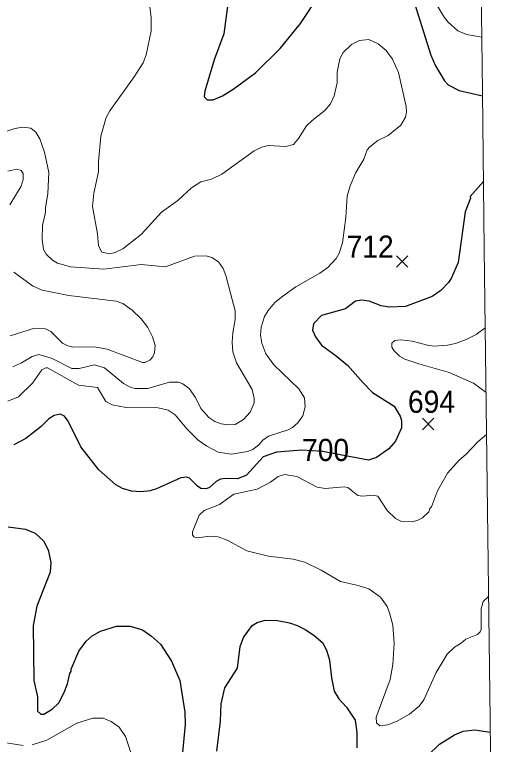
# Model space of a CAD drawing. Extents: x 265 to 291.4, y 7731.5 to 7759.6.
# Drawn here: x 289.561 to 291.321, y 7743.657 to 7746.284 of the extents above; entities that cross this region are included whole.
import ezdxf
from ezdxf.enums import TextEntityAlignment as Align

# ---------------------------------------------------------------- set-up
doc = ezdxf.new("R2010")
doc.units = 0
doc.header["$LTSCALE"] = 0.032
for name, color, linetype, lineweight in [('1', 7, 'Continuous', 25), ('2', 7, 'Continuous', 13), ('21', 7, 'Continuous', 25), ('61', 7, 'Continuous', 13), ('63', 7, 'Continuous', 25)]:
    doc.layers.add(name, color=color, linetype=linetype, lineweight=lineweight)

msp = doc.modelspace()

# ---------------------------------------------------------------- linework, layer by layer
at = {"layer": '1'}
for points in [[(290.2756, 7745.9765), (290.3098, 7745.9916), (290.348, 7746.0155), (290.4276, 7746.0744), (290.5166, 7746.1611), (290.5906, 7746.2518), (290.725, 7746.4554)], [(290.9876, 7746.3679), (291.0599, 7746.1372), (291.0759, 7746.0991), (291.1085, 7746.045), (291.122, 7746.0314), (291.1618, 7746.0099), (291.2452, 7745.9917)], [(290.3281, 7746.3218), (290.3146, 7746.2144), (290.2788, 7746.1213), (290.2462, 7746.0084), (290.243, 7745.9877), (290.2541, 7745.9773), (290.2756, 7745.9765)], [(291.249, 7745.683), (291.2015, 7745.6289), (291.2023, 7745.6225), (291.1825, 7745.574), (291.1578, 7745.3911), (291.1331, 7745.3338), (291.1236, 7745.3195), (291.095, 7745.2908), (291.0639, 7745.2693), (290.9685, 7745.2335), (290.9096, 7745.2304), (290.881, 7745.2351), (290.838, 7745.2526), (290.8094, 7745.2558), (290.7879, 7745.2526), (290.7521, 7745.2248), (290.6654, 7745.2009), (290.6376, 7745.1707), (290.6336, 7745.1484), (290.6439, 7745.1238), (290.6654, 7745.0943), (290.7187, 7745.0561), (290.7609, 7745.0211), (290.8141, 7744.9591), (290.8499, 7744.9233), (290.9279, 7744.8748), (290.9494, 7744.839), (290.9534, 7744.8231), (290.9541, 7744.7968), (290.9319, 7744.7483), (290.908, 7744.7213), (290.8635, 7744.6902), (290.8348, 7744.6807), (290.6693, 7744.7117), (290.5956, 7744.7157), (290.5039, 7744.7085), (290.4554, 7744.6918), (290.3957, 7744.6258), (290.3639, 7744.6131), (290.3194, 7744.6147), (290.3018, 7744.6115), (290.2868, 7744.6035), (290.2621, 7744.582), (290.251, 7744.5773), (290.2319, 7744.5781), (290.2199, 7744.586), (290.1905, 7744.6155), (290.181, 7744.6186), (290.1595, 7744.617), (290.0712, 7744.5765), (290.0489, 7744.5701), (290.0155, 7744.5661), (289.9821, 7744.5685), (289.9495, 7744.5781), (289.9256, 7744.5916), (289.8643, 7744.6449), (289.7999, 7744.7276), (289.7538, 7744.8207), (289.7403, 7744.8382), (289.7251, 7744.8453), (289.7037, 7744.8414), (289.6838, 7744.8286), (289.6567, 7744.8016), (289.6018, 7744.7579), (289.5581, 7744.7356)], [(289.5382, 7744.4405), (289.6003, 7744.4317), (289.6353, 7744.4174)], [(289.6353, 7744.4174), (289.6655, 7744.3903), (289.6822, 7744.3569), (289.6909, 7744.3124), (289.6885, 7744.2774), (289.6408, 7744.1549), (289.6273, 7744.0849)], [(290.2891, 7743.6331), (290.3018, 7743.7412), (290.305, 7743.8033), (290.3178, 7743.8606), (290.3639, 7743.9322), (290.3727, 7744.0101), (290.3854, 7744.0419), (290.4164, 7744.0849), (290.4339, 7744.096), (290.4626, 7744.1048), (290.5071, 7744.1032), (290.5501, 7744.0952), (290.5787, 7744.0857), (290.6073, 7744.0713), (290.6384, 7744.0507), (290.6702, 7744.0228), (290.6853, 7743.9926), (290.6948, 7743.9608), (290.702, 7743.8972), (290.7115, 7743.8494), (290.7282, 7743.8208), (290.7561, 7743.7914), (290.7871, 7743.7444), (290.7935, 7743.6999), (290.7927, 7743.645)], [(289.6273, 7744.0849), (289.6305, 7743.8876), (289.6432, 7743.8287), (289.6432, 7743.777), (289.6559, 7743.7667), (289.6663, 7743.7659), (289.6965, 7743.7842), (289.7196, 7743.8072), (289.7386, 7743.8415), (289.7514, 7743.8749), (289.7593, 7743.913), (289.7641, 7743.9194), (289.7641, 7743.9282), (289.7919, 7743.9926), (289.8182, 7744.0284), (289.8405, 7744.0483), (289.8707, 7744.0642), (289.928, 7744.0825), (289.9773, 7744.0825), (290.0219, 7744.069), (290.0537, 7744.0467), (290.0863, 7744.0181), (290.1253, 7743.9568), (290.1555, 7743.8876), (290.1738, 7743.7731), (290.1746, 7743.7285), (290.165, 7743.6283)], [(291.048, 7743.6156), (291.0902, 7743.6577), (291.1443, 7743.6919), (291.1753, 7743.7054), (291.2183, 7743.7094), (291.273, 7743.7019)]]:
    msp.add_lwpolyline(points, dxfattribs=at)
at = {"layer": '2'}
for points in [[(291.2427, 7746.2019), (291.188, 7746.212), (291.1562, 7746.2255), (291.122, 7746.2558), (291.1069, 7746.2741), (291.0409, 7746.3854), (290.9868, 7746.492), (290.9725, 7746.5302), (290.9645, 7746.5652), (290.9597, 7746.6368), (290.9709, 7746.6925), (290.982, 7746.7243), (291.0011, 7746.7521), (291.0297, 7746.7792), (291.0767, 7746.8086), (291.1467, 7746.8396), (291.2199, 7746.8818), (291.2343, 7746.8892)], [(290.0401, 7746.3743), (290.0521, 7746.2725), (290.0521, 7746.2247), (290.0346, 7746.1388), (290.0234, 7746.1102), (289.9916, 7746.0593), (289.9033, 7745.9368), (289.8906, 7745.9129), (289.8715, 7745.8461), (289.8628, 7745.7554), (289.8628, 7745.7172), (289.846, 7745.6409), (289.8413, 7745.5931), (289.8596, 7745.4945), (289.8635, 7745.4515), (289.8755, 7745.4285), (289.9025, 7745.4229), (289.9232, 7745.4269), (289.9503, 7745.4404), (290.0179, 7745.4937), (290.0895, 7745.5732), (290.1483, 7745.6146), (290.1977, 7745.6607), (290.2319, 7745.6822), (290.2701, 7745.691), (290.3066, 7745.7093), (290.4236, 7745.7936), (290.4514, 7745.8071), (290.4737, 7745.8127), (290.5373, 7745.8095), (290.5652, 7745.8166), (290.5827, 7745.8373), (290.6121, 7745.8827), (290.632, 7745.9026), (290.6773, 7745.9384), (290.6988, 7745.9622), (290.7115, 7745.9909), (290.7227, 7746.0386), (290.7227, 7746.0768), (290.7322, 7746.1245), (290.7434, 7746.1468), (290.7736, 7746.1762), (290.803, 7746.1905), (290.8364, 7746.1945), (290.8699, 7746.1778), (290.8985, 7746.1539), (290.9215, 7746.1229), (290.943, 7746.0752), (290.9709, 7745.9527), (290.9717, 7745.9336), (290.9677, 7745.9145), (290.951, 7745.8859), (290.9064, 7745.8485), (290.8683, 7745.8302), (290.8396, 7745.8079), (290.8301, 7745.7968), (290.8181, 7745.7634), (290.7895, 7745.7156), (290.7688, 7745.6679), (290.7577, 7745.6297), (290.7529, 7745.5534), (290.741, 7745.4627), (290.729, 7745.4245), (290.7187, 7745.4054), (290.6885, 7745.3736), (290.6598, 7745.3537), (290.5739, 7745.3036), (290.5262, 7745.2709), (290.4984, 7745.2479), (290.4737, 7745.2193), (290.4602, 7745.197), (290.4482, 7745.1588), (290.4466, 7745.1302), (290.4506, 7745.1015), (290.4649, 7745.0633)], [(289.6838, 7745.7156), (289.6687, 7745.7888), (289.6512, 7745.8365), (289.6368, 7745.8604), (289.6193, 7745.8755), (289.5907, 7745.8787), (289.5621, 7745.8739)], [(289.5621, 7745.8739), (289.5112, 7745.8572)], [(289.5438, 7745.5995), (289.5851, 7745.6663), (289.5923, 7745.6902), (289.5923, 7745.7117), (289.5843, 7745.722), (289.5684, 7745.7268), (289.5366, 7745.7204)], [(289.5541, 7745.0164), (289.5859, 7745.0299), (289.6241, 7745.0538), (289.648, 7745.0601), (289.6957, 7745.0458), (289.7673, 7745.01), (289.7928, 7745.01), (289.8484, 7745.0236), (289.885, 7745.0124), (289.9535, 7744.9559), (289.9773, 7744.9424), (289.9932, 7744.9376), (290.0409, 7744.9376), (290.1189, 7744.9607), (290.1507, 7744.9607), (290.1666, 7744.9551), (290.1897, 7744.9384), (290.212, 7744.9058), (290.2319, 7744.8661), (290.2597, 7744.8342), (290.2812, 7744.8191), (290.3051, 7744.8104), (290.3289, 7744.8072), (290.3544, 7744.8088), (290.3854, 7744.8271), (290.4093, 7744.8533), (290.4228, 7744.8867), (290.4236, 7744.9026), (290.4156, 7744.9345), (290.3599, 7745.0299), (290.3464, 7745.0697), (290.344, 7745.1047), (290.3464, 7745.1381), (290.3552, 7745.1858), (290.3552, 7745.2177), (290.3217, 7745.3449), (290.3122, 7745.3704), (290.2955, 7745.3934), (290.2708, 7745.4094), (290.2502, 7745.4157), (290.208, 7745.4141), (290.1046, 7745.3759), (290.0171, 7745.3847), (289.8819, 7745.3672), (289.7625, 7745.3759), (289.7148, 7745.3895), (289.6973, 7745.3998), (289.675, 7745.4213), (289.6655, 7745.4388), (289.6599, 7745.4746), (289.6615, 7745.5247), (289.6718, 7745.5724), (289.6718, 7745.5884), (289.6806, 7745.6393), (289.6838, 7745.7156)], [(289.5446, 7745.1278), (289.6321, 7745.1548), (289.6719, 7745.1532), (289.6909, 7745.1429), (289.7339, 7745.1015), (289.753, 7745.0912), (289.7705, 7745.0864), (289.8469, 7745.088), (289.8946, 7745.08), (290.0219, 7745.0315), (290.0298, 7745.0315), (290.0473, 7745.0403), (290.0584, 7745.0522), (290.0648, 7745.0665), (290.0672, 7745.0928), (290.0568, 7745.1238), (290.0401, 7745.1572), (290.0163, 7745.189), (289.9845, 7745.22), (289.9503, 7745.2439), (289.9264, 7745.2526), (289.7562, 7745.2725), (289.6607, 7745.2916), (289.6257, 7745.3075), (289.5581, 7745.3569)], [(291.2582, 7744.9232), (291.2135, 7744.9575), (291.126, 7744.9957), (291.0162, 7745.0267), (290.9653, 7745.0442), (290.947, 7745.0546), (290.9263, 7745.0753), (290.9192, 7745.0872), (290.9192, 7745.1015), (290.9295, 7745.1103), (290.951, 7745.1126), (290.9924, 7745.1079), (291.048, 7745.0936), (291.0719, 7745.0904), (291.1196, 7745.0943), (291.1483, 7745.0999), (291.1865, 7745.1142), (291.2223, 7745.1329), (291.2554, 7745.156)], [(290.4649, 7745.0633), (290.4944, 7745.0236), (290.5843, 7744.9369), (290.6041, 7744.905), (290.6073, 7744.8724), (290.5986, 7744.8398), (290.5803, 7744.8151)], [(290.5803, 7744.8151), (290.562, 7744.7976), (290.5453, 7744.7889), (290.4753, 7744.7666), (290.4546, 7744.7523), (290.4403, 7744.7356), (290.418, 7744.7189), (290.3989, 7744.7109), (290.3416, 7744.7022), (290.2939, 7744.7093), (290.2526, 7744.73), (290.2215, 7744.7523), (290.181, 7744.7929), (290.1388, 7744.843), (290.1141, 7744.8605), (290.0775, 7744.8684), (289.963, 7744.87), (289.9121, 7744.8796), (289.8898, 7744.8907), (289.8588, 7744.9416), (289.7912, 7744.9496), (289.6798, 7745.0124), (289.6734, 7745.0124), (289.6591, 7745.0053), (289.6249, 7744.9567), (289.5748, 7744.9082), (289.5366, 7744.8923)], [(291.2671, 7744.189), (291.2484, 7744.1715), (291.2405, 7744.1453), (291.2405, 7744.0706), (291.2373, 7744.0618), (291.227, 7744.0531), (291.1849, 7744.0364), (291.169, 7744.0212), (291.1451, 7744.0077), (291.118, 7743.9815), (291.079, 7743.9162), (291.0337, 7743.8176), (291.0178, 7743.7953), (290.9828, 7743.7659), (290.9383, 7743.7412), (290.9049, 7743.7277), (290.8762, 7743.7237), (290.8635, 7743.7349), (290.8627, 7743.7556), (290.9136, 7743.8908), (290.9231, 7743.9449), (290.9271, 7744.0213), (290.9231, 7744.0865), (290.9112, 7744.131), (290.9017, 7744.1533), (290.8786, 7744.1867), (290.8364, 7744.2177), (290.7983, 7744.2297), (290.7346, 7744.2432), (290.6646, 7744.2845), (290.6057, 7744.3132), (290.5644, 7744.3243), (290.4753, 7744.3347), (290.3973, 7744.3538), (290.3257, 7744.3927), (290.2939, 7744.4039), (290.2653, 7744.4062), (290.2176, 7744.4007), (290.2056, 7744.4047), (290.2008, 7744.4118), (290.2016, 7744.4222), (290.2255, 7744.4818), (290.243, 7744.4985), (290.2987, 7744.5208), (290.3504, 7744.5582), (290.4347, 7744.5757), (290.4817, 7744.6011), (290.5103, 7744.6218), (290.5326, 7744.629), (290.5771, 7744.6218), (290.6503, 7744.5828), (290.6789, 7744.5781), (290.7473, 7744.5844), (290.7609, 7744.5821), (290.7967, 7744.5534), (290.8133, 7744.551), (290.8524, 7744.5542), (290.8683, 7744.5502), (290.9017, 7744.4985), (290.9319, 7744.4699), (290.951, 7744.4611), (290.9908, 7744.458), (291.0099, 7744.4627), (291.0289, 7744.4723), (291.052, 7744.4946), (291.056, 7744.5057), (291.0623, 7744.5121), (291.083, 7744.5701), (291.1196, 7744.6338), (291.161, 7744.6799), (291.1849, 7744.7006), (291.2286, 7744.7467), (291.26, 7744.7727)], [(289.6241, 7743.6553), (289.6766, 7743.672), (289.7848, 7743.7341), (289.8421, 7743.7516), (289.8803, 7743.7516), (289.9089, 7743.7396), (289.9375, 7743.719), (289.9598, 7743.6856), (289.9797, 7743.6283)], [(289.5159, 7743.6649), (289.5923, 7743.6537)]]:
    msp.add_lwpolyline(points, dxfattribs=at)
at = {"layer": '21'}
for p, q in [((290.9358, 7745.4157), (290.977, 7745.3745)), ((290.977, 7745.4157), (290.9358, 7745.3745)), ((291.0293, 7744.831), (291.0705, 7744.7898)), ((291.0705, 7744.831), (291.0293, 7744.7898))]:
    msp.add_line(p, q, dxfattribs=at)
at = {"layer": '63', "lineweight": 13}
msp.add_lwpolyline([(291.3207, 7739.7916), (291.3138, 7740.3565), (291.3069, 7740.9214), (291.3, 7741.4863), (291.2932, 7742.0512), (291.2863, 7742.6161), (291.2794, 7743.181), (291.2725, 7743.7459), (291.2657, 7744.3108), (291.2588, 7744.8756), (291.2519, 7745.4405), (291.245, 7746.0054), (291.2382, 7746.5703)], dxfattribs=at)

# ---------------------------------------------------------------- texts
at = {"layer": '61', "width": 0.95}
for s, p in [('712', (290.8408, 7745.4085)), ('694', (291.0618, 7744.8505)), ('700', (290.6804, 7744.6769))]:
    msp.add_text(s, height=0.08, dxfattribs=at).set_placement(p, align=Align.CENTER)

doc.saveas('drawing.dxf')
